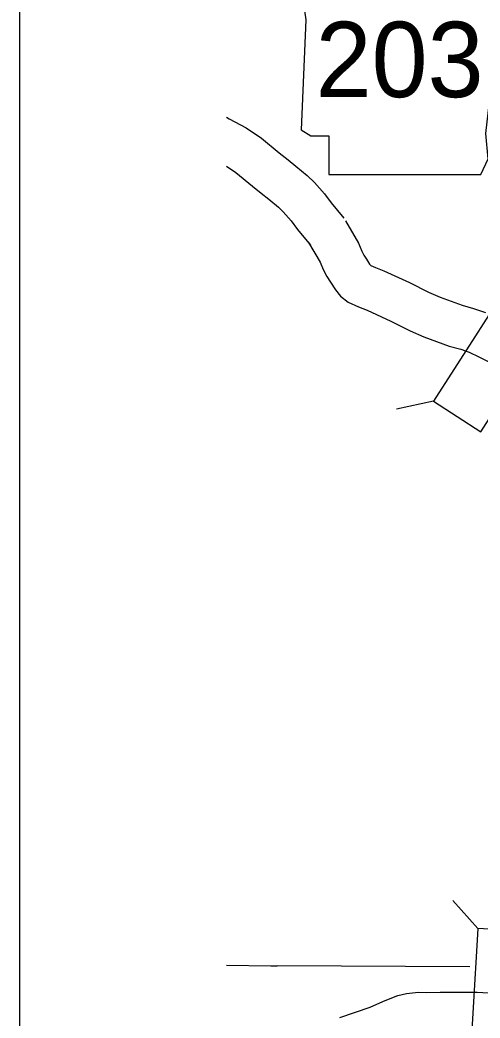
# Model space of a CAD drawing. Extents: x -492261 to -432772, y 1441225 to 1452922.
# Drawn here: x -459957.6 to -459877, y 1452284 to 1452458.8 of the extents above; entities that cross this region are included whole.
import ezdxf

# ---------------------------------------------------------------- set-up
doc = ezdxf.new("R2010")
doc.units = 0
for name, color, linetype in [('Default', 7, 'Continuous'), ('R_Border', 7, 'Continuous'), ('R_No Plot', 7, 'Continuous')]:
    doc.layers.add(name, color=color, linetype=linetype)

msp = doc.modelspace()

# ---------------------------------------------------------------- linework, layer by layer
at = {"layer": 'Default'}
for p, q in [((-459885.18, 1452392), (-459891.63, 1452390.6)), ((-459877.38, 1452299.64), (-459881.77, 1452304.58))]:
    msp.add_line(p, q, dxfattribs=at)
for points in [[(-459909.42, 1452471.46), (-459907.52, 1452458.77), (-459908.37, 1452439.53), (-459906.68, 1452438.47), (-459903.5, 1452438.47), (-459903.5, 1452431.7), (-459876.86, 1452431.7), (-459875.59, 1452434.45), (-459876.01, 1452438.89), (-459875.38, 1452443.97), (-459873.05, 1452447.99), (-459871.57, 1452450.95), (-459869.46, 1452454.12), (-459868.19, 1452457.5), (-459867.13, 1452460.25), (-459865.23, 1452462.58), (-459864.8, 1452464.06), (-459865.65, 1452465.12), (-459872.21, 1452465.12), (-459870.72, 1452468.08), (-459870.51, 1452469.98), (-459871.39, 1452471.44)], [(-459869.1, 1452416.98), (-459885.18, 1452392), (-459876.85, 1452386.64), (-459860.78, 1452411.62)], [(-459869.24, 1452269.41), (-459867.5, 1452299.06), (-459877.38, 1452299.64), (-459879.12, 1452269.99)]]:
    msp.add_lwpolyline(points, close=True, dxfattribs=at)
for points in [[(-459921.42, 1452441.74), (-459920.98, 1452441.47), (-459917.98, 1452439.88), (-459915.29, 1452438.03), (-459912.2, 1452435.51), (-459910.65, 1452434.27), (-459909.3, 1452433.16), (-459907.3, 1452431.55), (-459906.03, 1452430.29), (-459904.29, 1452428.31), (-459903.07, 1452426.72), (-459900.9, 1452424.03)], [(-459921.42, 1452433.15), (-459919.78, 1452432.02), (-459916.91, 1452429.67), (-459915.37, 1452428.45), (-459914.04, 1452427.35), (-459912.3, 1452425.95), (-459911.48, 1452425.14), (-459910.09, 1452423.56), (-459908.97, 1452422.09), (-459906.73, 1452419.31)], [(-459900.58, 1452423.56), (-459898.29, 1452419.65), (-459897.73, 1452418.27), (-459897.35, 1452417.58), (-459896.9, 1452416.85), (-459896.35, 1452416.02), (-459896.19, 1452415.84), (-459896.13, 1452415.79), (-459895.33, 1452415.41), (-459893.87, 1452414.84), (-459889.39, 1452412.78), (-459886.05, 1452411.12), (-459884.02, 1452410.21), (-459880.16, 1452408.81), (-459878.13, 1452408.26), (-459876.06, 1452407.53)], [(-459907.05, 1452419.78), (-459905.03, 1452416.33), (-459904.51, 1452415.04), (-459903.83, 1452413.81), (-459903.23, 1452412.83), (-459902.36, 1452411.5), (-459901.43, 1452410.42), (-459900.1, 1452409.36), (-459898.28, 1452408.51), (-459896.81, 1452407.94), (-459892.62, 1452406.02), (-459889.26, 1452404.34), (-459886.84, 1452403.25), (-459882.42, 1452401.66), (-459880.37, 1452401.09), (-459878.91, 1452400.58), (-459877.2, 1452399.78), (-459875.09, 1452398.71)], [(-459921.42, 1452293.22), (-459913.65, 1452293.12), (-459912.58, 1452293.12)], [(-459878.81, 1452292.95), (-459912.58, 1452293.12)], [(-459901.58, 1452284.06), (-459896.27, 1452285.9), (-459894.06, 1452286.89), (-459892.46, 1452287.53), (-459891.43, 1452287.92), (-459889.9, 1452288.3), (-459887.81, 1452288.5), (-459886.32, 1452288.47), (-459884.02, 1452288.52), (-459881.61, 1452288.52), (-459877.48, 1452288.53), (-459870.59, 1452288.13)]]:
    msp.add_lwpolyline(points, dxfattribs=at)
at = {"layer": 'R_Border'}
msp.add_line((-459957.64, 1450553.05), (-459957.64, 1452607.65), dxfattribs=at)
at = {"layer": 'R_No Plot'}
msp.add_lwpolyline([(-457618.44, 1452607.65), (-457618.44, 1452508.85), (-457261.12, 1452508.85), (-457261.12, 1452479.65), (-457029.12, 1452479.65), (-457029.12, 1452236.32), (-456795.84, 1452236.32), (-456795.84, 1450553.05), (-459957.64, 1450553.05), (-459957.64, 1452607.65)], close=True, dxfattribs=at)

# ---------------------------------------------------------------- texts
at = {"layer": 'Default'}
msp.add_text('203', height=13.2, dxfattribs=at).set_placement((-459905.83, 1452445.24))

doc.saveas('drawing.dxf')
